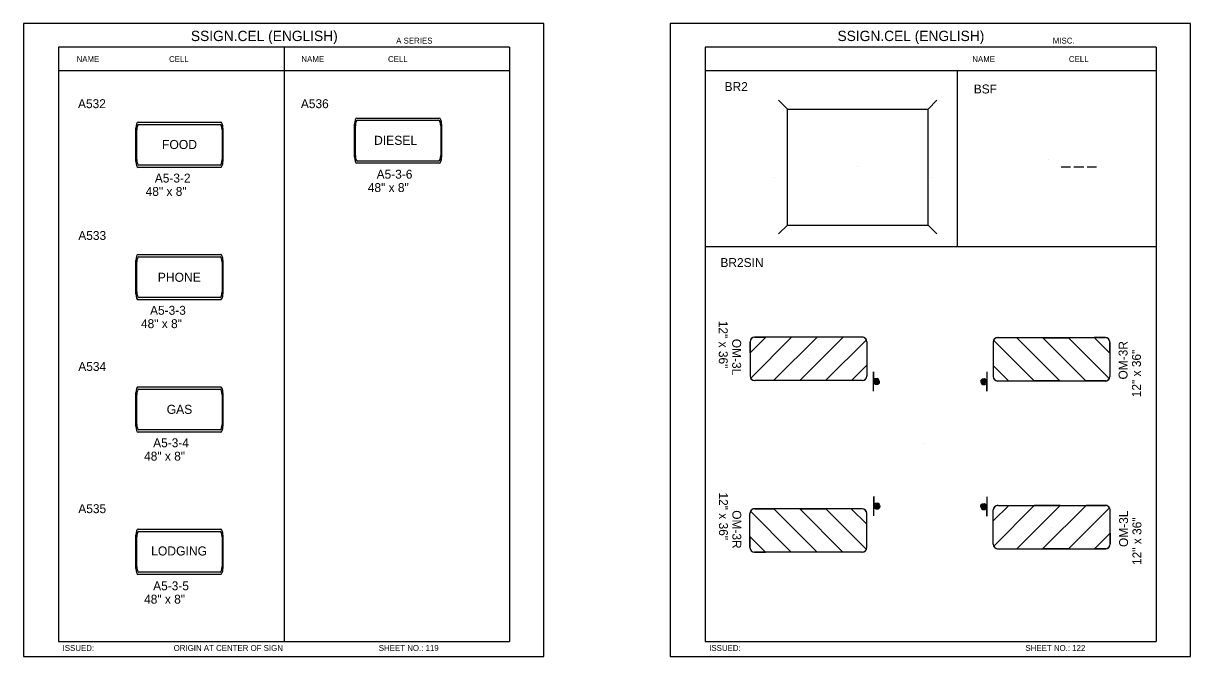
# Model space of a CAD drawing. Extents: x -5299 to 22597, y -19549 to -1808.
# Drawn here: x -4301 to -2729, y -15644 to -14791 of the extents above; entities that cross this region are included whole.
import ezdxf

# ---------------------------------------------------------------- set-up
doc = ezdxf.new("R2010")
doc.units = 0
for name, color, linetype in [('Level 1', 7, 'Continuous'), ('Level 2', 7, 'Continuous'), ('Level 3', 7, 'Continuous'), ('Level 60', 7, 'Continuous')]:
    doc.layers.add(name, color=color, linetype=linetype)

msp = doc.modelspace()

# ---------------------------------------------------------------- linework, layer by layer
at = {"layer": 'Level 1'}
for p, q in [((-3646, -14823.4), (-4253, -14823.4)), ((-4253, -14823.4), (-4253, -15623.4)), ((-3949.5, -14823.4), (-3949.5, -15623.4)), ((-3646, -14823.4), (-3646, -15623.4)), ((-2775.3, -14823.4), (-3382.3, -14823.4)), ((-3382.3, -14823.4), (-3382.3, -15623.4)), ((-2775.3, -14823.4), (-2775.3, -15623.4)), ((-3646, -14855.1), (-4253, -14855.1)), ((-2775.3, -14855.1), (-3382.3, -14855.1)), ((-3043.2, -14855.1), (-3043.2, -15091.9)), ((-3271.7, -14906.7), (-3283.6, -14894.7)), ((-3082.3, -14906.7), (-3070.4, -14894.7)), ((-3271.7, -15062.8), (-3271.7, -14906.7)), ((-3271.7, -14906.7), (-3082.3, -14906.7)), ((-3139.1, -14906.7), (-3098.1, -14906.7)), ((-3082.3, -15062.8), (-3082.3, -14906.7)), ((-4146, -14924.2), (-4034.8, -14924.2)), ((-4145.1, -14927.2), (-4035.7, -14927.2)), ((-3854.5, -14971.5), (-3854.5, -14926.8)), ((-3853.4, -14969.1), (-3853.4, -14929.2)), ((-3851.6, -14918.7), (-3740.4, -14918.7)), ((-3850.7, -14921.7), (-3741.3, -14921.7)), ((-3738.6, -14929.2), (-3738.6, -14969.1)), ((-3737.5, -14926.8), (-3737.5, -14971.5)), ((-4148.9, -14977), (-4148.9, -14932.3)), ((-4147.8, -14974.6), (-4147.8, -14934.7)), ((-4033, -14934.7), (-4033, -14974.6)), ((-4031.9, -14932.3), (-4031.9, -14977)), ((-4090.4, -14954.6), (-4090.4, -14954.6)), ((-4090.4, -14954.6), (-4090.4, -14954.6)), ((-3796, -14949.1), (-3796, -14949.1)), ((-3796, -14949.1), (-3796, -14949.1)), ((-3741.3, -14976.6), (-3850.7, -14976.6)), ((-2919.8, -14974.1), (-2919.8, -14974.1)), ((-4034.8, -14985.1), (-4146, -14985.1)), ((-4035.7, -14982.1), (-4145.1, -14982.1)), ((-3740.4, -14979.6), (-3851.6, -14979.6)), ((-3176.8, -14984.4), (-3176.8, -14984.4)), ((-2903.3, -14984.2), (-2890.6, -14984.2)), ((-2886.3, -14984.2), (-2872.5, -14984.2)), ((-2868.3, -14984.2), (-2855.6, -14984.2)), ((-3289.5, -14998.2), (-3289.5, -14998.2)), ((-3077.8, -14998.2), (-3077.8, -14998.2)), ((-3283.6, -15074.7), (-3271.7, -15062.8)), ((-3271.7, -15062.8), (-3082.3, -15062.8)), ((-3139.1, -15062.8), (-3092.8, -15062.8)), ((-3070.4, -15074.7), (-3082.3, -15062.8)), ((-4146, -15102.4), (-4034.8, -15102.4)), ((-2775.3, -15091.9), (-3382.3, -15091.9)), ((-4148.9, -15155.2), (-4148.9, -15110.5)), ((-4147.8, -15152.8), (-4147.8, -15112.9)), ((-4145.1, -15105.4), (-4035.7, -15105.4)), ((-4033, -15112.9), (-4033, -15152.8)), ((-4031.9, -15110.5), (-4031.9, -15155.2)), ((-4090.4, -15132.8), (-4090.4, -15132.8)), ((-4090.4, -15132.8), (-4090.4, -15132.8)), ((-4034.8, -15163.3), (-4146, -15163.3)), ((-4035.7, -15160.3), (-4145.1, -15160.3)), ((-3301, -15213.5), (-3322, -15234.6)), ((-3266.4, -15213.8), (-3321.2, -15268.6)), ((-3316, -15213.5), (-3301, -15213.5)), ((-3170.4, -15213.5), (-3315.8, -15213.5)), ((-3289.8, -15271.7), (-3231.5, -15213.8)), ((-3231.5, -15213.8), (-3266.4, -15213.8)), ((-3196.7, -15213.8), (-3254.7, -15271.7)), ((-3171.5, -15213.5), (-3196.7, -15213.8)), ((-2989.1, -15214.1), (-2843.8, -15214.1)), ((-2988.1, -15214.1), (-2962.8, -15214.4)), ((-2858.6, -15214.1), (-2837.5, -15235.2)), ((-2843.5, -15214.1), (-2858.6, -15214.1)), ((-3322, -15219.7), (-3322, -15265.8)), ((-3322, -15234.6), (-3322, -15220)), ((-3219.8, -15271.7), (-3165.2, -15217.1)), ((-3164.7, -15219.7), (-3164.7, -15265.8)), ((-2994.8, -15220.4), (-2994.8, -15266.4)), ((-2939.7, -15272.4), (-2994.3, -15217.8)), ((-2962.8, -15214.4), (-2904.8, -15272.4)), ((-2928, -15214.4), (-2893.2, -15214.4)), ((-2869.8, -15272.4), (-2928, -15214.4)), ((-2893.2, -15214.4), (-2838.3, -15269.2)), ((-2837.5, -15220.4), (-2837.5, -15266.4)), ((-2837.5, -15235.2), (-2837.5, -15220.6)), ((-3243.2, -15242.8), (-3243.2, -15242.8)), ((-2916.3, -15243.4), (-2916.3, -15243.4)), ((-3185.5, -15272), (-3164.7, -15251.2)), ((-3164.7, -15251.2), (-3164.7, -15265.8)), ((-2974, -15272.6), (-2994.8, -15251.8)), ((-2994.8, -15251.8), (-2994.8, -15266.4)), ((-3316, -15272), (-3289.8, -15271.7)), ((-3171, -15272), (-3315.8, -15272)), ((-3254.7, -15271.7), (-3219.8, -15271.7)), ((-3171.2, -15272), (-3185.5, -15272)), ((-3164.7, -15265.8), (-3164.7, -15266)), ((-2994.8, -15266.4), (-2994.8, -15266.6)), ((-2988.6, -15272.6), (-2843.8, -15272.6)), ((-2988.3, -15272.6), (-2974, -15272.6)), ((-2904.8, -15272.4), (-2939.7, -15272.4)), ((-2843.5, -15272.6), (-2869.8, -15272.4)), ((-4148.9, -15333.4), (-4148.9, -15288.7)), ((-4147.8, -15331), (-4147.8, -15291.1)), ((-4146, -15280.6), (-4034.8, -15280.6)), ((-4145.1, -15283.6), (-4035.7, -15283.6)), ((-4033, -15291.1), (-4033, -15331)), ((-4031.9, -15288.7), (-4031.9, -15333.4)), ((-4090.4, -15311), (-4090.4, -15311)), ((-4090.4, -15311), (-4090.4, -15311)), ((-4035.7, -15338.5), (-4145.1, -15338.5)), ((-4034.8, -15341.5), (-4146, -15341.5)), ((-3086.9, -15357.4), (-3086.9, -15357.4)), ((-3266.5, -15502.8), (-3321.4, -15448)), ((-3316.2, -15444.6), (-3289.9, -15444.9)), ((-3171.1, -15444.6), (-3315.9, -15444.6)), ((-3289.9, -15444.9), (-3231.7, -15502.8)), ((-3196.9, -15502.8), (-3254.8, -15444.9)), ((-3254.8, -15444.9), (-3220, -15444.9)), ((-3220, -15444.9), (-3165.4, -15499.5)), ((-3171.4, -15444.6), (-3185.7, -15444.6)), ((-3185.7, -15444.6), (-3164.9, -15465.4)), ((-2973.7, -15440), (-2994.5, -15460.8)), ((-2994.5, -15446.2), (-2994.5, -15446)), ((-2994.5, -15492.2), (-2994.5, -15446.2)), ((-2994.5, -15460.8), (-2994.5, -15446.2)), ((-2939.4, -15440.2), (-2994, -15494.8)), ((-2988.3, -15440), (-2843.5, -15440)), ((-2988, -15440), (-2973.7, -15440)), ((-2962.5, -15498.2), (-2904.6, -15440.2)), ((-2904.6, -15440.2), (-2939.4, -15440.2)), ((-2869.5, -15440.2), (-2927.7, -15498.2)), ((-2892.9, -15498.2), (-2838, -15443.4)), ((-2843.2, -15440), (-2869.5, -15440.2)), ((-2837.2, -15492.2), (-2837.2, -15446.2)), ((-3322.2, -15496.9), (-3322.2, -15450.8)), ((-3164.9, -15450.8), (-3164.9, -15450.6)), ((-3164.9, -15496.9), (-3164.9, -15450.8)), ((-3164.9, -15465.4), (-3164.9, -15450.8)), ((-4148.9, -15524.8), (-4148.9, -15480.1)), ((-4146, -15472), (-4034.8, -15472)), ((-4145.1, -15475), (-4035.7, -15475)), ((-4031.9, -15480.1), (-4031.9, -15524.8)), ((-3243.4, -15473.9), (-3243.4, -15473.9)), ((-2916, -15469.2), (-2916, -15469.2)), ((-2858.3, -15498.5), (-2837.2, -15477.4)), ((-2837.2, -15477.4), (-2837.2, -15492)), ((-4147.8, -15522.4), (-4147.8, -15482.5)), ((-4033, -15482.5), (-4033, -15522.4)), ((-3301.1, -15503.1), (-3322.2, -15482)), ((-3322.2, -15482), (-3322.2, -15496.6)), ((-4090.4, -15502.4), (-4090.4, -15502.4)), ((-4090.4, -15502.4), (-4090.4, -15502.4)), ((-3316.2, -15503.1), (-3301.1, -15503.1)), ((-3170.6, -15503.1), (-3315.9, -15503.1)), ((-3231.7, -15502.8), (-3266.5, -15502.8)), ((-3171.6, -15503.1), (-3196.9, -15502.8)), ((-2988.8, -15498.5), (-2843.5, -15498.5)), ((-2987.8, -15498.5), (-2962.5, -15498.2)), ((-2927.7, -15498.2), (-2892.9, -15498.2)), ((-2843.2, -15498.5), (-2858.3, -15498.5)), ((-4034.8, -15532.9), (-4146, -15532.9)), ((-4035.7, -15529.9), (-4145.1, -15529.9)), ((-4253, -15623.4), (-3646, -15623.4)), ((-3382.3, -15623.4), (-2775.3, -15623.4))]:
    msp.add_line(p, q, dxfattribs=at)
for centre, radius, start, end in [((-3315.8, -15219.8), 6.24, 90, 180), ((-3315.8, -15219.7), 6.13, 93.0907, 183.0907), ((-3171.1, -15220.2), 6.55, 26.6664, 93.2943), ((-3171.1, -15219.8), 6.36, 0.5054, 90.5054), ((-2988.4, -15220.4), 6.36, 89.4946, 179.4946), ((-2843.8, -15220.4), 6.24, 0, 90), ((-2988.4, -15220.8), 6.55, 86.7057, 153.3336), ((-2843.7, -15220.3), 6.13, 356.9093, 86.9093), ((-3315.8, -15265.8), 6.24, 180, 270), ((-3316, -15266.1), 5.86, 206.4031, 269.2905), ((-3171.1, -15265.7), 6.28, 268.6953, 358.1007), ((-3171, -15265.8), 6.24, 270, 0), ((-2988.6, -15266.4), 6.24, 180, 270), ((-2988.5, -15266.3), 6.28, 181.8993, 271.3047), ((-2843.8, -15266.4), 6.24, 270, 0), ((-2843.5, -15266.7), 5.86, 270.7095, 333.5969), ((-3315.9, -15450.8), 6.24, 90, 180), ((-3316.2, -15450.5), 5.86, 90.7095, 153.5969), ((-3171.2, -15450.9), 6.28, 1.8993, 91.3047), ((-3171.1, -15450.8), 6.24, 0, 90), ((-2988.3, -15446.2), 6.24, 90, 180), ((-2988.2, -15446.3), 6.28, 88.6953, 178.1007), ((-2843.5, -15446.2), 6.24, 0, 90), ((-2843.2, -15445.9), 5.86, 26.4031, 89.2905), ((-3315.9, -15496.8), 6.24, 180, 270), ((-3316, -15496.9), 6.13, 176.9093, 266.9093), ((-3171.2, -15496.8), 6.36, 269.4946, 359.4946), ((-2988.2, -15492.2), 6.36, 180.5054, 270.5054), ((-2988.1, -15491.8), 6.55, 206.6664, 273.2943), ((-2843.5, -15492.2), 6.24, 270, 0), ((-2843.4, -15492.3), 6.13, 273.0907, 3.0907), ((-3171.3, -15496.4), 6.55, 266.7057, 333.3336)]:
    msp.add_arc(centre, radius, start, end, dxfattribs=at)
for centre, major_axis, start_param, end_param in [((-4146, -14932.3), (0, -8.13), 3.141593, 4.712389), ((-4145.1, -14934.7), (0, -7.52), 3.141593, 4.712389), ((-4035.7, -14934.7), (0, 7.52), 4.712389, 6.283185), ((-4034.8, -14932.3), (0, 8.13), 4.712389, 6.283185), ((-3851.6, -14926.8), (0, -8.13), 3.141593, 4.712389), ((-3850.7, -14929.2), (0, -7.52), 3.141593, 4.712389), ((-3741.3, -14929.2), (0, 7.52), 4.712389, 6.283185), ((-3740.4, -14926.8), (0, 8.13), 4.712389, 6.283185), ((-4146, -14977), (0, -8.13), 4.712389, 6.283185), ((-4145.1, -14974.6), (0, -7.52), 4.712389, 6.283185), ((-4035.7, -14974.6), (0, 7.52), 3.141593, 4.712389), ((-4034.8, -14977), (0, 8.13), 3.141593, 4.712389), ((-3851.6, -14971.5), (0, -8.13), 4.712389, 6.283185), ((-3850.7, -14969.1), (0, -7.52), 4.712389, 6.283185), ((-3741.3, -14969.1), (0, 7.52), 3.141593, 4.712389), ((-3740.4, -14971.5), (0, 8.13), 3.141593, 4.712389), ((-4146, -15110.5), (0, -8.13), 3.141593, 4.712389), ((-4034.8, -15110.5), (0, 8.13), 4.712389, 6.283185), ((-4145.1, -15112.9), (0, -7.52), 3.141593, 4.712389), ((-4035.7, -15112.9), (0, 7.52), 4.712389, 6.283185), ((-4146, -15155.2), (0, -8.13), 4.712389, 6.283185), ((-4145.1, -15152.8), (0, -7.52), 4.712389, 6.283185), ((-4035.7, -15152.8), (0, 7.52), 3.141593, 4.712389), ((-4034.8, -15155.2), (0, 8.13), 3.141593, 4.712389), ((-4146, -15288.7), (0, -8.13), 3.141593, 4.712389), ((-4145.1, -15291.1), (0, -7.52), 3.141593, 4.712389), ((-4035.7, -15291.1), (0, 7.52), 4.712389, 6.283185), ((-4034.8, -15288.7), (0, 8.13), 4.712389, 6.283185), ((-4146, -15333.4), (0, -8.13), 4.712389, 6.283185), ((-4145.1, -15331), (0, -7.52), 4.712389, 6.283185), ((-4035.7, -15331), (0, 7.52), 3.141593, 4.712389), ((-4034.8, -15333.4), (0, 8.13), 3.141593, 4.712389), ((-4146, -15480.1), (0, -8.13), 3.141593, 4.712389), ((-4145.1, -15482.5), (0, -7.52), 3.141593, 4.712389), ((-4035.7, -15482.5), (0, 7.52), 4.712389, 6.283185), ((-4034.8, -15480.1), (0, 8.13), 4.712389, 6.283185), ((-4146, -15524.8), (0, -8.13), 4.712389, 6.283185), ((-4145.1, -15522.4), (0, -7.52), 4.712389, 6.283185), ((-4035.7, -15522.4), (0, 7.52), 3.141593, 4.712389), ((-4034.8, -15524.8), (0, 8.13), 3.141593, 4.712389)]:
    msp.add_ellipse(centre, major_axis=major_axis, ratio=0.36, start_param=start_param, end_param=end_param, dxfattribs=at)
at = {"layer": 'Level 2'}
for points in [[(-3156, -15286.5), (-3156, -15260.4), (-3156, -15273.1), (-3155.1, -15275.7), (-3153.1, -15277.1), (-3150, -15276.7), (-3147.8, -15275), (-3147.6, -15273.4), (-3148.9, -15270.7), (-3150.9, -15269.3), (-3153.9, -15269.5), (-3155.6, -15271.2), (-3155.1, -15274), (-3152.6, -15276), (-3150.6, -15275.4), (-3149.2, -15274.2), (-3150, -15271.5), (-3152.5, -15270.4), (-3153.9, -15272), (-3153.9, -15274), (-3152.6, -15274.8), (-3151.1, -15274.6), (-3150.9, -15273.2), (-3151.8, -15272.5), (-3152.8, -15272.5), (-3153.1, -15273.4), (-3152.1, -15273.5)], [(-3003.2, -15260.3), (-3003.2, -15286.3), (-3003.2, -15273.7), (-3004.1, -15271), (-3006.2, -15269.6), (-3009.3, -15270.1), (-3011.5, -15271.8), (-3011.6, -15273.4), (-3010.4, -15276), (-3008.4, -15277.4), (-3005.4, -15277.3), (-3003.7, -15275.6), (-3004.1, -15272.8), (-3006.6, -15270.7), (-3008.7, -15271.4), (-3010.1, -15272.6), (-3009.3, -15275.3), (-3006.8, -15276.4), (-3005.4, -15274.8), (-3005.4, -15272.8), (-3006.6, -15272), (-3008.2, -15272.1), (-3008.4, -15273.5), (-3007.4, -15274.3), (-3006.5, -15274.3), (-3006.2, -15273.4), (-3007.1, -15273.2)], [(-3155.3, -15454.3), (-3155.3, -15428.2), (-3155.3, -15440.9), (-3154.4, -15443.5), (-3152.4, -15444.9), (-3149.3, -15444.5), (-3147.1, -15442.7), (-3146.9, -15441.2), (-3148.2, -15438.5), (-3150.2, -15437.1), (-3153.2, -15437.3), (-3154.9, -15439), (-3154.4, -15441.8), (-3151.9, -15443.8), (-3149.9, -15443.2), (-3148.5, -15442), (-3149.3, -15439.3), (-3151.8, -15438.2), (-3153.2, -15439.8), (-3153.2, -15441.8), (-3151.9, -15442.6), (-3150.3, -15442.4), (-3150.2, -15441), (-3151.1, -15440.2), (-3152.1, -15440.2), (-3152.4, -15441.2), (-3151.4, -15441.3)], [(-3003.4, -15428.5), (-3003.4, -15454.6), (-3003.4, -15442), (-3004.4, -15439.3), (-3006.4, -15437.9), (-3009.5, -15438.4), (-3011.7, -15440.1), (-3011.9, -15441.6), (-3010.6, -15444.3), (-3008.6, -15445.7), (-3005.6, -15445.5), (-3003.9, -15443.8), (-3004.4, -15441), (-3006.9, -15439), (-3008.9, -15439.6), (-3010.3, -15440.9), (-3009.5, -15443.5), (-3007, -15444.6), (-3005.6, -15443), (-3005.6, -15441), (-3006.9, -15440.2), (-3008.4, -15440.4), (-3008.6, -15441.8), (-3007.7, -15442.6), (-3006.7, -15442.6), (-3006.4, -15441.6), (-3007.3, -15441.5)]]:
    msp.add_lwpolyline(points, dxfattribs=at)
at = {"layer": 'Level 60'}
for points in [[(-4300.5, -15643.6), (-3599.5, -15643.6), (-3599.5, -14791.3), (-4300.5, -14791.3)], [(-3429.8, -15643.6), (-2728.8, -15643.6), (-2728.8, -14791.3), (-3429.8, -14791.3)]]:
    msp.add_lwpolyline(points, close=True, dxfattribs=at)

# ---------------------------------------------------------------- texts
at = {"layer": 'Level 1'}
for s, p in [('DIESEL', (-3828.3, -14954.8)), ('FOOD', (-4113.8, -14960.4)), ('PHONE', (-4119.5, -15139.1)), ('GAS', (-4107.5, -15316.9)), ('LODGING', (-4128.4, -15507.5))]:
    msp.add_text(s, height=12.2, dxfattribs=at).set_placement(p)
at = {"layer": 'Level 2'}
for s, p in [('A532', (-4226.9, -14905.4)), ('A536', (-3926.8, -14905.4)), ('A533', (-4226.5, -15082.8)), ('A534', (-4226.5, -15259.1)), ('A535', (-4226.5, -15450.5))]:
    msp.add_text(s, height=12, dxfattribs=at).set_placement(p)
at = {"layer": 'Level 3'}
for s, height, p in [('SSIGN.CEL (ENGLISH)', 13.857, (-4074.9, -14815.1)), ('SSIGN.CEL (ENGLISH)', 13.857, (-3204.3, -14815.1)), ('A SERIES', 7.92, (-3798.5, -14818.5)), ('MISC.', 7.92, (-2914.4, -14818.5)), ('NAME', 7.92, (-4228.8, -14843.3)), ('CELL', 7.92, (-4104.3, -14843.3)), ('NAME', 7.92, (-3926.1, -14843.3)), ('CELL', 7.92, (-3809.5, -14843.3)), ('NAME', 7.92, (-3022.8, -14843.3)), ('CELL', 7.92, (-2892.7, -14843.3)), ('BR2', 12, (-3356.3, -14882.4)), ('BSF', 12, (-3020.8, -14885.6)), ('A5-3-2', 12, (-4123.5, -15005.5)), ('A5-3-6', 12, (-3824.8, -15000.3)), ('48" x 8"', 12, (-3836.7, -15018.3)), ('48" x 8"', 12, (-4135.8, -15023.5)), ('BR2SIN', 12, (-3361.9, -15119.2)), ('A5-3-3', 12, (-4129.9, -15183.5)), ('48" x 8"', 12, (-4142.1, -15201.5)), ('A5-3-4', 12, (-4125.7, -15361.8)), ('48" x 8"', 12, (-4137.9, -15379.8)), ('A5-3-5', 12, (-4125.7, -15554.3)), ('48" x 8"', 12, (-4137.9, -15572.3)), ('ISSUED:', 7.92, (-4247.6, -15635.9)), ('ORIGIN AT CENTER OF SIGN', 7.918, (-4098.1, -15635.9)), ('SHEET NO.: 119', 7.918, (-3821.9, -15635.9)), ('ISSUED:', 7.92, (-3377, -15635.9)), ('SHEET NO.: 122', 7.918, (-2951.2, -15635.9))]:
    msp.add_text(s, height=height, dxfattribs=at).set_placement(p)
for s, rotation, p in [('12" x 36"', 270, (-3364.1, -15191.6)), ('OM-3L', 270, (-3346.1, -15215.9)), ('OM-3R', 90, (-2813.8, -15270.6)), ('12" x 36"', 90, (-2795.8, -15294.5)), ('12" x 36"', 270, (-3363.9, -15422.7)), ('OM-3R', 270, (-3345.9, -15446.6)), ('OM-3L', 90, (-2813.1, -15496.1)), ('12" x 36"', 90, (-2795.1, -15520.3))]:
    msp.add_text(s, height=12, rotation=rotation, dxfattribs=at).set_placement(p)

doc.saveas('drawing.dxf')
